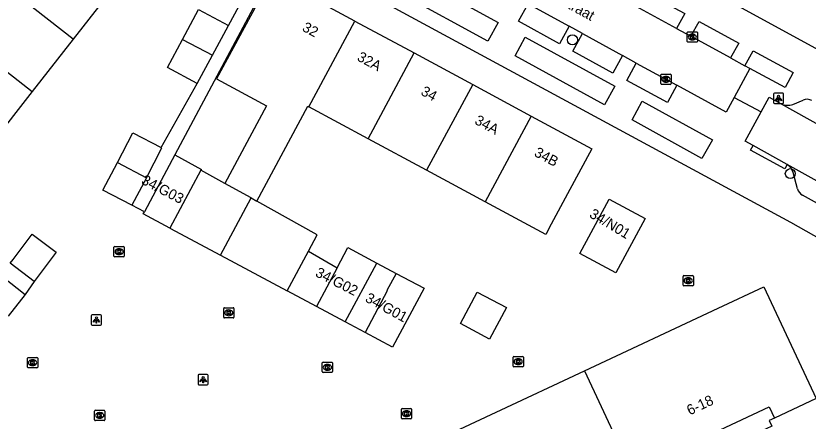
# Model space of a CAD drawing. Extents: x 158352 to 159489, y 383828 to 384597.
# Drawn here: x 158988.7 to 159066, y 383935.6 to 383975.2 of the extents above; entities that cross this region are included whole.
import ezdxf

# ---------------------------------------------------------------- set-up
doc = ezdxf.new("R2010")
doc.units = 0
for name, color, linetype in [('IMGEO_Boom', 7, 'Continuous'), ('IMGEO_Kolk', 7, 'Continuous'), ('IMGEO_Lichtpunt', 7, 'Continuous'), ('IMGEO_Openbare_ruimte_label', 7, 'Continuous'), ('IMGEO_Pand', 7, 'Continuous'), ('IMGEO_Pand_nummerreeks', 7, 'Continuous'), ('IMGEO_Rijbaan_lokaal_open', 7, 'Continuous'), ('IMGEO_Voetpad_open', 7, 'Continuous')]:
    doc.layers.add(name, color=color, linetype=linetype)

msp = doc.modelspace()

# ---------------------------------------------------------------- linework, layer by layer
at = {"layer": 'IMGEO_Boom'}
for centre in [(159043.03, 383972.815), (159064.291, 383959.768)]:
    msp.add_circle(centre, 0.489, dxfattribs=at)
at = {"layer": 'IMGEO_Kolk'}
for p, q in [((159054.232, 383972.662), (159054.232, 383973.514)), ((159054.307, 383973.588), (159055.159, 383973.588)), ((159054.72, 383973.368), (159054.745, 383973.368)), ((159055.233, 383973.514), (159055.233, 383972.662)), ((159055.159, 383972.588), (159054.307, 383972.588)), ((159054.743, 383972.808), (159054.718, 383972.808)), ((159051.658, 383968.543), (159051.658, 383969.395)), ((159051.733, 383969.469), (159052.585, 383969.469)), ((159052.146, 383969.249), (159052.171, 383969.249)), ((159052.659, 383969.395), (159052.659, 383968.543)), ((159052.585, 383968.469), (159051.733, 383968.469)), ((159052.169, 383968.689), (159052.144, 383968.689)), ((158998.306, 383951.732), (158998.306, 383952.584)), ((158998.381, 383952.658), (158999.233, 383952.658)), ((158998.794, 383952.438), (158998.819, 383952.438)), ((158999.307, 383952.584), (158999.307, 383951.732)), ((158999.233, 383951.658), (158998.381, 383951.658)), ((158998.817, 383951.878), (158998.792, 383951.878)), ((159053.831, 383948.9), (159053.831, 383949.752)), ((159053.906, 383949.826), (159054.758, 383949.826)), ((159054.319, 383949.606), (159054.344, 383949.606)), ((159054.832, 383949.752), (159054.832, 383948.9)), ((159054.758, 383948.826), (159053.906, 383948.826)), ((159054.342, 383949.046), (159054.317, 383949.046)), ((159009.013, 383945.771), (159009.013, 383946.623)), ((159009.088, 383946.697), (159009.94, 383946.697)), ((159009.501, 383946.477), (159009.526, 383946.477)), ((159010.014, 383946.623), (159010.014, 383945.771)), ((159009.94, 383945.697), (159009.088, 383945.697)), ((159009.524, 383945.917), (159009.499, 383945.917)), ((158989.862, 383940.913), (158989.862, 383941.765)), ((158989.937, 383941.839), (158990.789, 383941.839)), ((158990.35, 383941.619), (158990.375, 383941.619)), ((158990.863, 383941.765), (158990.863, 383940.913)), ((159018.703, 383941.386), (159019.555, 383941.386)), ((159037.243, 383941.008), (159037.243, 383941.86)), ((159037.318, 383941.934), (159038.17, 383941.934)), ((159037.731, 383941.714), (159037.756, 383941.714)), ((159038.244, 383941.86), (159038.244, 383941.008)), ((158990.789, 383940.839), (158989.937, 383940.839)), ((158990.373, 383941.059), (158990.348, 383941.059)), ((159018.628, 383940.46), (159018.628, 383941.312)), ((159019.139, 383940.606), (159019.114, 383940.606)), ((159019.116, 383941.166), (159019.141, 383941.166)), ((159019.629, 383941.312), (159019.629, 383940.46)), ((159038.17, 383940.934), (159037.318, 383940.934)), ((159037.754, 383941.154), (159037.729, 383941.154)), ((159019.555, 383940.386), (159018.703, 383940.386)), ((159026.345, 383935.936), (159026.345, 383936.788)), ((159026.42, 383936.862), (159027.272, 383936.862)), ((159027.346, 383936.788), (159027.346, 383935.936)), ((158996.414, 383935.764), (158996.414, 383936.616)), ((158996.489, 383936.69), (158997.341, 383936.69)), ((158996.902, 383936.47), (158996.927, 383936.47)), ((158997.415, 383936.616), (158997.415, 383935.764)), ((159026.856, 383936.082), (159026.831, 383936.082)), ((159026.833, 383936.642), (159026.858, 383936.642)), ((158997.341, 383935.69), (158996.489, 383935.69)), ((158996.925, 383935.91), (158996.9, 383935.91)), ((159027.272, 383935.862), (159026.42, 383935.862))]:
    msp.add_line(p, q, dxfattribs=at)
for points in [[(159054.232, 383972.662), (159054.232, 383973.514)], [(159054.307, 383973.588), (159055.159, 383973.588)], [(159054.553, 383973.288), (159054.676, 383973.288), (159054.676, 383973.137), (159054.806, 383973.288), (159054.97, 383973.288), (159054.824, 383973.137), (159054.977, 383972.888), (159054.825, 383972.888), (159054.74, 383973.052), (159054.676, 383972.985), (159054.676, 383972.888), (159054.553, 383972.888), (159054.553, 383973.288)], [(159055.233, 383973.514), (159055.233, 383972.662)], [(159055.159, 383972.588), (159054.307, 383972.588)], [(159051.658, 383968.543), (159051.658, 383969.395)], [(159051.733, 383969.469), (159052.585, 383969.469)], [(159052.659, 383969.395), (159052.659, 383968.543)], [(159052.585, 383968.469), (159051.733, 383968.469)], [(159051.979, 383969.169), (159052.102, 383969.169), (159052.102, 383969.018), (159052.232, 383969.169), (159052.396, 383969.169), (159052.25, 383969.018), (159052.403, 383968.769), (159052.251, 383968.769), (159052.166, 383968.933), (159052.102, 383968.866), (159052.102, 383968.769), (159051.979, 383968.769), (159051.979, 383969.169)], [(158998.306, 383951.732), (158998.306, 383952.584)], [(158998.381, 383952.658), (158999.233, 383952.658)], [(158998.627, 383952.358), (158998.75, 383952.358), (158998.75, 383952.207), (158998.88, 383952.358), (158999.044, 383952.358), (158998.898, 383952.207), (158999.051, 383951.958), (158998.899, 383951.958), (158998.814, 383952.122), (158998.75, 383952.055), (158998.75, 383951.958), (158998.627, 383951.958), (158998.627, 383952.358)], [(158999.307, 383952.584), (158999.307, 383951.732)], [(158999.233, 383951.658), (158998.381, 383951.658)], [(159053.831, 383948.9), (159053.831, 383949.752)], [(159053.906, 383949.826), (159054.758, 383949.826)], [(159054.152, 383949.526), (159054.275, 383949.526), (159054.275, 383949.375), (159054.405, 383949.526), (159054.569, 383949.526), (159054.423, 383949.375), (159054.576, 383949.126), (159054.424, 383949.126), (159054.339, 383949.29), (159054.275, 383949.223), (159054.275, 383949.126), (159054.152, 383949.126), (159054.152, 383949.526)], [(159054.832, 383949.752), (159054.832, 383948.9)], [(159054.758, 383948.826), (159053.906, 383948.826)], [(159009.013, 383945.771), (159009.013, 383946.623)], [(159009.088, 383946.697), (159009.94, 383946.697)], [(159009.334, 383946.397), (159009.457, 383946.397), (159009.457, 383946.246), (159009.587, 383946.397), (159009.751, 383946.397), (159009.605, 383946.246), (159009.758, 383945.997), (159009.606, 383945.997), (159009.521, 383946.161), (159009.457, 383946.094), (159009.457, 383945.997), (159009.334, 383945.997), (159009.334, 383946.397)], [(159010.014, 383946.623), (159010.014, 383945.771)], [(159009.94, 383945.697), (159009.088, 383945.697)], [(158989.862, 383940.913), (158989.862, 383941.765)], [(158989.937, 383941.839), (158990.789, 383941.839)], [(158990.183, 383941.539), (158990.306, 383941.539), (158990.306, 383941.388), (158990.436, 383941.539), (158990.6, 383941.539), (158990.454, 383941.388), (158990.607, 383941.139), (158990.455, 383941.139), (158990.37, 383941.303), (158990.306, 383941.236), (158990.306, 383941.139), (158990.183, 383941.139), (158990.183, 383941.539)], [(158990.863, 383941.765), (158990.863, 383940.913)], [(159018.703, 383941.386), (159019.555, 383941.386)], [(159037.243, 383941.008), (159037.243, 383941.86)], [(159037.318, 383941.934), (159038.17, 383941.934)], [(159037.564, 383941.634), (159037.687, 383941.634), (159037.687, 383941.483), (159037.817, 383941.634), (159037.981, 383941.634), (159037.835, 383941.483), (159037.988, 383941.234), (159037.836, 383941.234), (159037.751, 383941.398), (159037.687, 383941.331), (159037.687, 383941.234), (159037.564, 383941.234), (159037.564, 383941.634)], [(159038.244, 383941.86), (159038.244, 383941.008)], [(158990.789, 383940.839), (158989.937, 383940.839)], [(159018.628, 383940.46), (159018.628, 383941.312)], [(159018.949, 383941.086), (159019.072, 383941.086), (159019.072, 383940.935), (159019.202, 383941.086), (159019.366, 383941.086), (159019.22, 383940.935), (159019.373, 383940.686), (159019.221, 383940.686), (159019.136, 383940.85), (159019.072, 383940.783), (159019.072, 383940.686), (159018.949, 383940.686), (159018.949, 383941.086)], [(159019.629, 383941.312), (159019.629, 383940.46)], [(159038.17, 383940.934), (159037.318, 383940.934)], [(159019.555, 383940.386), (159018.703, 383940.386)], [(159026.345, 383935.936), (159026.345, 383936.788)], [(159026.42, 383936.862), (159027.272, 383936.862)], [(159027.346, 383936.788), (159027.346, 383935.936)], [(158996.414, 383935.764), (158996.414, 383936.616)], [(158996.489, 383936.69), (158997.341, 383936.69)], [(158996.735, 383936.39), (158996.858, 383936.39), (158996.858, 383936.239), (158996.988, 383936.39), (158997.152, 383936.39), (158997.006, 383936.239), (158997.159, 383935.99), (158997.007, 383935.99), (158996.922, 383936.154), (158996.858, 383936.087), (158996.858, 383935.99), (158996.735, 383935.99), (158996.735, 383936.39)], [(158997.415, 383936.616), (158997.415, 383935.764)], [(159026.666, 383936.562), (159026.789, 383936.562), (159026.789, 383936.411), (159026.919, 383936.562), (159027.083, 383936.562), (159026.937, 383936.411), (159027.09, 383936.162), (159026.938, 383936.162), (159026.853, 383936.326), (159026.789, 383936.259), (159026.789, 383936.162), (159026.666, 383936.162), (159026.666, 383936.562)], [(158997.341, 383935.69), (158996.489, 383935.69)], [(159027.272, 383935.862), (159026.42, 383935.862)]]:
    msp.add_lwpolyline(points, dxfattribs=at)
for centre, start, end in [((159054.309, 383973.512), 91.55205, 178.44795), ((159054.309, 383973.512), 91.55205, 178.44795), ((159055.157, 383973.512), 1.55205, 88.44795), ((159055.157, 383973.512), 1.55205, 88.44795), ((159054.309, 383972.664), 181.55205, 268.44795), ((159054.309, 383972.664), 181.55205, 268.44795), ((159055.157, 383972.664), 271.55205, 358.44795), ((159055.157, 383972.664), 271.55205, 358.44795), ((159051.735, 383969.393), 91.55205, 178.44795), ((159051.735, 383969.393), 91.55205, 178.44795), ((159052.583, 383969.393), 1.55205, 88.44795), ((159052.583, 383969.393), 1.55205, 88.44795), ((159051.735, 383968.545), 181.55205, 268.44795), ((159051.735, 383968.545), 181.55205, 268.44795), ((159052.583, 383968.545), 271.55205, 358.44795), ((159052.583, 383968.545), 271.55205, 358.44795), ((158998.383, 383952.582), 91.55205, 178.44795), ((158998.383, 383952.582), 91.55205, 178.44795), ((158999.231, 383952.582), 1.55205, 88.44795), ((158999.231, 383952.582), 1.55205, 88.44795), ((158998.383, 383951.734), 181.55205, 268.44795), ((158998.383, 383951.734), 181.55205, 268.44795), ((158999.231, 383951.734), 271.55205, 358.44795), ((158999.231, 383951.734), 271.55205, 358.44795), ((159053.908, 383949.75), 91.55205, 178.44795), ((159053.908, 383949.75), 91.55205, 178.44795), ((159054.756, 383949.75), 1.55205, 88.44795), ((159054.756, 383949.75), 1.55205, 88.44795), ((159053.908, 383948.902), 181.55205, 268.44795), ((159053.908, 383948.902), 181.55205, 268.44795), ((159054.756, 383948.902), 271.55205, 358.44795), ((159054.756, 383948.902), 271.55205, 358.44795), ((159009.09, 383946.621), 91.55205, 178.44795), ((159009.09, 383946.621), 91.55205, 178.44795), ((159009.938, 383946.621), 1.55205, 88.44795), ((159009.938, 383946.621), 1.55205, 88.44795), ((159009.09, 383945.773), 181.55205, 268.44795), ((159009.09, 383945.773), 181.55205, 268.44795), ((159009.938, 383945.773), 271.55205, 358.44795), ((159009.938, 383945.773), 271.55205, 358.44795), ((158989.939, 383941.763), 91.55205, 178.44795), ((158989.939, 383941.763), 91.55205, 178.44795), ((158990.787, 383941.763), 1.55205, 88.44795), ((158990.787, 383941.763), 1.55205, 88.44795), ((159018.705, 383941.31), 91.55205, 178.44795), ((159018.705, 383941.31), 91.55205, 178.44795), ((159019.553, 383941.31), 1.55205, 88.44795), ((159019.553, 383941.31), 1.55205, 88.44795), ((159037.32, 383941.858), 91.55205, 178.44795), ((159037.32, 383941.858), 91.55205, 178.44795), ((159038.168, 383941.858), 1.55205, 88.44795), ((159038.168, 383941.858), 1.55205, 88.44795), ((158989.939, 383940.915), 181.55205, 268.44795), ((158989.939, 383940.915), 181.55205, 268.44795), ((158990.787, 383940.915), 271.55205, 358.44795), ((158990.787, 383940.915), 271.55205, 358.44795), ((159037.32, 383941.01), 181.55205, 268.44795), ((159037.32, 383941.01), 181.55205, 268.44795), ((159038.168, 383941.01), 271.55205, 358.44795), ((159038.168, 383941.01), 271.55205, 358.44795), ((159018.705, 383940.462), 181.55205, 268.44795), ((159018.705, 383940.462), 181.55205, 268.44795), ((159019.553, 383940.462), 271.55205, 358.44795), ((159019.553, 383940.462), 271.55205, 358.44795), ((159026.422, 383936.786), 91.55205, 178.44795), ((159026.422, 383936.786), 91.55205, 178.44795), ((159027.27, 383936.786), 1.55205, 88.44795), ((159027.27, 383936.786), 1.55205, 88.44795), ((158996.491, 383936.614), 91.55205, 178.44795), ((158996.491, 383936.614), 91.55205, 178.44795), ((158997.339, 383936.614), 1.55205, 88.44795), ((158997.339, 383936.614), 1.55205, 88.44795), ((158996.491, 383935.766), 181.55205, 268.44795), ((158996.491, 383935.766), 181.55205, 268.44795), ((158997.339, 383935.766), 271.55205, 358.44795), ((158997.339, 383935.766), 271.55205, 358.44795), ((159026.422, 383935.938), 181.55205, 268.44795), ((159026.422, 383935.938), 181.55205, 268.44795), ((159027.27, 383935.938), 271.55205, 358.44795), ((159027.27, 383935.938), 271.55205, 358.44795)]:
    msp.add_arc(centre, 0.0765, start, end, dxfattribs=at)
for centre, major_axis, ratio, start_param, end_param in [((159054.719, 383973.088), (-0.387, 0.002), 0.722429, 4.712389, 7.853982), ((159054.744, 383973.088), (-0.39, 0.002), 0.717154, 1.570796, 4.712389), ((159052.145, 383968.969), (-0.387, 0.002), 0.722429, 4.712389, 7.853982), ((159052.17, 383968.969), (-0.39, 0.002), 0.717154, 1.570796, 4.712389), ((158998.793, 383952.158), (-0.387, 0.002), 0.722429, 4.712389, 7.853982), ((158998.818, 383952.158), (-0.39, 0.002), 0.717154, 1.570796, 4.712389), ((159054.318, 383949.326), (-0.387, 0.002), 0.722429, 4.712389, 7.853982), ((159054.343, 383949.326), (-0.39, 0.002), 0.717154, 1.570796, 4.712389), ((159009.5, 383946.197), (-0.387, 0.002), 0.722429, 4.712389, 7.853982), ((159009.525, 383946.197), (-0.39, 0.002), 0.717154, 1.570796, 4.712389), ((158990.349, 383941.339), (-0.387, 0.002), 0.722429, 4.712389, 7.853982), ((158990.374, 383941.339), (-0.39, 0.002), 0.717154, 1.570796, 4.712389), ((159037.73, 383941.434), (-0.387, 0.002), 0.722429, 4.712389, 7.853982), ((159037.755, 383941.434), (-0.39, 0.002), 0.717154, 1.570796, 4.712389), ((159019.115, 383940.886), (-0.387, 0.002), 0.722429, 4.712389, 7.853982), ((159019.14, 383940.886), (-0.39, 0.002), 0.717154, 1.570796, 4.712389), ((158996.901, 383936.19), (-0.387, 0.002), 0.722429, 4.712389, 7.853982), ((158996.926, 383936.19), (-0.39, 0.002), 0.717154, 1.570796, 4.712389), ((159026.832, 383936.362), (-0.387, 0.002), 0.722429, 4.712389, 7.853982), ((159026.857, 383936.362), (-0.39, 0.002), 0.717154, 1.570796, 4.712389)]:
    msp.add_ellipse(centre, major_axis=major_axis, ratio=ratio, start_param=start_param, end_param=end_param, dxfattribs=at)
at = {"layer": 'IMGEO_Lichtpunt'}
for p, q in [((159062.645, 383967.509), (159062.645, 383966.702)), ((159062.645, 383967.509), (159062.645, 383966.702)), ((159063.547, 383967.604), (159062.739, 383967.604)), ((159063.547, 383967.604), (159062.739, 383967.604)), ((159063.641, 383966.702), (159063.641, 383967.509)), ((159063.641, 383966.702), (159063.641, 383967.509)), ((159062.739, 383966.608), (159063.547, 383966.608)), ((159062.739, 383966.608), (159063.547, 383966.608)), ((158996.995, 383946.001), (158996.187, 383946.001)), ((158996.995, 383946.001), (158996.187, 383946.001)), ((158996.093, 383945.906), (158996.093, 383945.099)), ((158996.093, 383945.906), (158996.093, 383945.099)), ((158997.089, 383945.099), (158997.089, 383945.906)), ((158997.089, 383945.099), (158997.089, 383945.906)), ((158996.187, 383945.005), (158996.995, 383945.005)), ((158996.187, 383945.005), (158996.995, 383945.005)), ((159006.505, 383940.086), (159006.505, 383939.279)), ((159006.505, 383940.086), (159006.505, 383939.279)), ((159007.407, 383940.181), (159006.599, 383940.181)), ((159007.407, 383940.181), (159006.599, 383940.181)), ((159007.501, 383939.279), (159007.501, 383940.086)), ((159007.501, 383939.279), (159007.501, 383940.086)), ((159006.599, 383939.185), (159007.407, 383939.185)), ((159006.599, 383939.185), (159007.407, 383939.185))]:
    msp.add_line(p, q, dxfattribs=at)
for points in [[(159063.019, 383967.173), (159063.058, 383967.145), (159062.87, 383966.883), (159062.832, 383966.91), (159063.019, 383967.173)], [(159063.121, 383967.125), (159063.168, 383967.125), (159063.168, 383966.803), (159063.121, 383966.803), (159063.121, 383967.125)], [(159063.231, 383967.145), (159063.269, 383967.172), (159063.456, 383966.91), (159063.417, 383966.882), (159063.231, 383967.145)], [(158996.467, 383945.57), (158996.506, 383945.542), (158996.318, 383945.28), (158996.28, 383945.307), (158996.467, 383945.57)], [(158996.569, 383945.522), (158996.616, 383945.522), (158996.616, 383945.2), (158996.569, 383945.2), (158996.569, 383945.522)], [(158996.679, 383945.542), (158996.717, 383945.569), (158996.904, 383945.307), (158996.865, 383945.279), (158996.679, 383945.542)], [(159006.879, 383939.75), (159006.918, 383939.722), (159006.73, 383939.46), (159006.692, 383939.487), (159006.879, 383939.75)], [(159006.981, 383939.702), (159007.028, 383939.702), (159007.028, 383939.38), (159006.981, 383939.38), (159006.981, 383939.702)], [(159007.091, 383939.722), (159007.129, 383939.749), (159007.316, 383939.487), (159007.277, 383939.459), (159007.091, 383939.722)]]:
    msp.add_lwpolyline(points, dxfattribs=at)
for centre in [(159063.144, 383967.307), (158996.592, 383945.704), (159007.004, 383939.884)]:
    msp.add_circle(centre, 0.0994, dxfattribs=at)
for centre, start, end in [((159062.739, 383967.509), 90, 180), ((159062.739, 383967.509), 90, 180), ((159063.547, 383967.509), 0, 90), ((159063.547, 383967.509), 0, 90), ((159062.739, 383966.702), 180, 270), ((159062.739, 383966.702), 180, 270), ((159063.547, 383966.702), 270, 0), ((159063.547, 383966.702), 270, 360), ((158996.187, 383945.906), 90, 180), ((158996.187, 383945.906), 90, 180), ((158996.995, 383945.906), 0, 90), ((158996.995, 383945.906), 0, 90), ((158996.187, 383945.099), 180, 270), ((158996.187, 383945.099), 180, 270), ((158996.995, 383945.099), 270, 0), ((158996.995, 383945.099), 270, 360), ((159006.599, 383940.086), 90, 180), ((159006.599, 383940.086), 90, 180), ((159007.407, 383940.086), 0, 90), ((159007.407, 383940.086), 0, 90), ((159006.599, 383939.279), 180, 270), ((159006.599, 383939.279), 180, 270), ((159007.407, 383939.279), 270, 0), ((159007.407, 383939.279), 270, 360)]:
    msp.add_arc(centre, 0.0946, start, end, dxfattribs=at)
at = {"layer": 'IMGEO_Pand'}
for points in [[(158994.317, 383972.887), (158986.865, 383978.704)], [(158998.321, 383978.008), (158994.317, 383972.887)], [(159021.815, 383974.65), (159015.936, 383977.82), (159015.499, 383977.01), (159013.269, 383978.213), (159008.306, 383969.01), (159013.194, 383966.374), (159009.12, 383958.818)], [(159004.989, 383972.86), (159006.557, 383975.768), (159009.47, 383974.197)], [(159017.308, 383966.291), (159021.815, 383974.65)], [(159021.815, 383974.65), (159027.585, 383971.539)], [(159007.915, 383971.314), (159009.47, 383974.197)], [(158982.869, 383973.585), (158990.329, 383967.786)], [(158994.317, 383972.887), (158990.329, 383967.786)], [(159006.426, 383968.552), (159003.513, 383970.123), (159004.989, 383972.86)], [(159004.989, 383972.86), (159007.915, 383971.314)], [(159023.113, 383963.161), (159027.585, 383971.539)], [(159027.585, 383971.539), (159033.314, 383968.449)], [(159006.426, 383968.552), (159007.915, 383971.314)], [(159033.314, 383968.449), (159028.807, 383960.091)], [(159033.314, 383968.449), (159039.017, 383965.374)], [(158990.329, 383967.786), (158986.331, 383962.673)], [(159012.238, 383957.081), (159017.227, 383966.335), (159017.308, 383966.291)], [(159023.113, 383963.161), (159017.308, 383966.291)], [(159039.017, 383965.374), (159034.51, 383957.016)], [(159039.017, 383965.374), (159044.933, 383962.184), (159042.56, 383957.784), (159040.974, 383954.842), (159040.426, 383953.826), (159034.51, 383957.016)], [(158998.643, 383960.867), (159000.151, 383963.744), (159002.902, 383962.314)], [(159028.807, 383960.091), (159023.113, 383963.161)], [(159001.462, 383959.363), (159002.986, 383962.271), (159002.902, 383962.314)], [(159004.237, 383961.61), (159001.268, 383956.043)], [(159004.237, 383961.61), (159006.828, 383960.186), (159006.791, 383960.116)], [(159000.059, 383956.686), (158997.224, 383958.159), (158998.643, 383960.867)], [(158998.643, 383960.867), (159001.462, 383959.363)], [(159006.791, 383960.116), (159003.765, 383954.445)], [(159009.12, 383958.818), (159006.791, 383960.116)], [(159034.51, 383957.016), (159028.807, 383960.091)], [(159001.462, 383959.363), (159000.059, 383956.686)], [(159011.676, 383957.394), (159009.12, 383958.818)], [(159008.696, 383951.814), (159011.676, 383957.394)], [(159011.676, 383957.394), (159012.238, 383957.081)], [(159017.273, 383952.221), (159018.119, 383953.805), (159012.238, 383957.081)], [(159043.753, 383951.977), (159046.616, 383957.287), (159050.129, 383955.392), (159047.266, 383950.082), (159043.753, 383951.977)], [(159003.765, 383954.445), (159001.158, 383955.837), (159001.268, 383956.043)], [(158988.471, 383951.405), (158990.338, 383953.876), (158992.681, 383952.105), (158990.526, 383949.252)], [(159003.765, 383954.445), (159008.696, 383951.814)], [(159015.203, 383948.341), (159017.273, 383952.221)], [(159017.273, 383952.221), (159020.07, 383950.596)], [(159020.07, 383950.596), (159021.122, 383952.557), (159023.935, 383951.054)], [(158984.631, 383951.929), (158989.64, 383947.992)], [(158990.526, 383949.252), (158988.182, 383951.022), (158988.471, 383951.405)], [(159008.696, 383951.814), (159015.203, 383948.341)], [(159020.847, 383945.328), (159023.935, 383951.054)], [(159023.935, 383951.054), (159025.83, 383950.042)], [(159020.07, 383950.596), (159018.057, 383946.818)], [(159025.83, 383950.042), (159024.927, 383948.357), (159024.971, 383948.333), (159022.8, 383944.285)], [(159025.83, 383950.042), (159028.556, 383948.586), (159025.491, 383942.848), (159022.8, 383944.285)], [(159018.057, 383946.818), (159018.048, 383946.823), (159015.203, 383948.341)], [(159044.205, 383940.528), (159057.262, 383946.636), (159061.709, 383948.723), (159066.812, 383937.845)], [(158989.64, 383947.992), (158987.979, 383945.879)], [(159032.098, 383945.147), (159033.743, 383948.226), (159036.588, 383946.707), (159034.943, 383943.627), (159032.098, 383945.147)], [(159020.847, 383945.328), (159018.057, 383946.818)], [(159022.8, 383944.285), (159020.847, 383945.328)], [(159026.991, 383932.475), (159044.205, 383940.528)], [(159044.205, 383940.528), (159049.303, 383929.63)], [(159066.812, 383937.845), (159062.739, 383935.934)], [(159053.193, 383931.455), (159052.677, 383932.555), (159062.223, 383937.033), (159062.739, 383935.934)]]:
    msp.add_lwpolyline(points, dxfattribs=at)
at = {"layer": 'IMGEO_Rijbaan_lokaal_open'}
for points in [[(159038.7, 383976.327), (159042.71, 383974.135)], [(159053.2, 383973.922), (159049.247, 383976.073)], [(159044.012, 383973.422), (159042.71, 383974.135)], [(159053.2, 383973.922), (159054.597, 383973.163)], [(159044.012, 383973.422), (159047.922, 383971.284)], [(159058.471, 383971.056), (159054.597, 383973.163)], [(159049.263, 383970.551), (159047.922, 383971.284)], [(159058.471, 383971.056), (159059.868, 383970.295)], [(159049.263, 383970.551), (159053.224, 383968.385)], [(159060.347, 383970.035), (159058.804, 383967.2)], [(159060.347, 383970.035), (159059.868, 383970.295)], [(159058.804, 383967.2), (159058.022, 383965.762), (159053.224, 383968.385)], [(159061.442, 383965.778), (159062.233, 383967.232), (159063.409, 383966.587)], [(159063.409, 383966.587), (159079.014, 383957.85), (159081.167, 383956.663)], [(159060.663, 383962.507), (159059.896, 383962.934), (159061.442, 383965.778)], [(159063.987, 383960.657), (159060.663, 383962.507)], [(159077.31, 383953.242), (159063.987, 383960.657)]]:
    msp.add_lwpolyline(points, dxfattribs=at)
at = {"layer": 'IMGEO_Voetpad_open'}
for points in [[(159009.47, 383974.197), (159013.854, 383982.326)], [(159014.965, 383981.725), (159004.237, 383961.61)], [(159077.838, 383947.064), (159071.597, 383950.894), (159064.335, 383954.998), (159014.965, 383981.725)], [(159082.318, 383963.502), (159052.18, 383979.979)], [(159027.419, 383979.092), (159035.784, 383974.501), (159034.781, 383972.7), (159026.415, 383977.282), (159027.419, 383979.092)], [(159049.247, 383976.073), (159050.035, 383977.522), (159053.988, 383975.372), (159053.2, 383973.922)], [(159042.71, 383974.135), (159041.772, 383972.425), (159037.765, 383974.623), (159038.7, 383976.327)], [(159054.597, 383973.163), (159055.385, 383974.612), (159059.259, 383972.505), (159058.471, 383971.056)], [(159038.438, 383973.079), (159047.175, 383968.288), (159046.17, 383966.472), (159037.45, 383971.264), (159038.438, 383973.079)], [(159047.922, 383971.284), (159046.982, 383969.57), (159043.074, 383971.712), (159044.012, 383973.422)], [(159059.868, 383970.295), (159060.657, 383971.744), (159064.573, 383969.614), (159063.784, 383968.164), (159060.347, 383970.035)], [(159053.224, 383968.385), (159052.303, 383966.692), (159048.338, 383968.849), (159049.263, 383970.551)], [(159002.902, 383962.314), (159006.426, 383968.552)], [(159058.804, 383967.2), (159061.442, 383965.778)], [(159064.53, 383966.525), (159065.54, 383966.942)], [(159049.838, 383966.837), (159056.688, 383963.067), (159055.675, 383961.25), (159048.855, 383965.019), (159049.838, 383966.837)], [(159063.987, 383960.657), (159063.746, 383960.221), (159060.422, 383962.07), (159060.663, 383962.507)], [(159064.994, 383958.278), (159064.571, 383959.877)], [(159074.182, 383952.816), (159065.475, 383957.66)], [(159001.268, 383956.043), (159000.059, 383956.686)], [(158990.526, 383949.252), (158989.64, 383947.992)], [(159062.739, 383935.934), (159062.241, 383935.701), (159062.499, 383935.148), (159060.272, 383934.105), (159060.014, 383934.655), (159055.874, 383932.713), (159056.136, 383932.153), (159053.916, 383931.106), (159053.652, 383931.67), (159053.193, 383931.455)]]:
    msp.add_lwpolyline(points, dxfattribs=at)
for centre, radius, start, end in [((159065.922, 383966.013), 1.005, 61.41506, 112.35031), ((159064.034, 383967.729), 1.302, 241.29579, 292.37285), ((159063.317, 383959.547), 1.297, 14.75536, 58.89035), ((159065.965, 383958.537), 1.005, 194.96353, 240.82494)]:
    msp.add_arc(centre, radius, start, end, dxfattribs=at)

# ---------------------------------------------------------------- texts
at = {"layer": 'IMGEO_Openbare_ruimte_label'}
msp.add_text('Venstraat', height=1, rotation=331.38497, dxfattribs=at).set_placement((159039.815, 383977.385))
at = {"layer": 'IMGEO_Pand_nummerreeks'}
for s, rotation, p in [('32', 331.66724, (159016.589, 383973.741)), ('32A', 331.6652, (159021.948, 383970.851)), ('34', 331.6652, (159028.165, 383967.498)), ('34A', 331.6652, (159033.414, 383964.668)), ('34B', 331.66724, (159039.223, 383961.536)), ('34/G03', 332.35479, (159000.897, 383958.827)), ('34/N01', 329.11857, (159044.601, 383955.576)), ('34/G02', 333.09391, (159017.868, 383949.807)), ('34/G01', 331.32685, (159022.736, 383947.345)), ('6-18', 25.13113, (159054.479, 383936.184))]:
    msp.add_text(s, height=1, rotation=rotation, dxfattribs=at).set_placement(p)

doc.saveas('drawing.dxf')
